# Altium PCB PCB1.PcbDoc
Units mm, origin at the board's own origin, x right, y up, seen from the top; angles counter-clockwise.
Board outline 33.5 x 35.78 mm, 2 copper layers (Top Layer, Bottom Layer); 48 components, 15 nets, 227 pads, 57 vias.
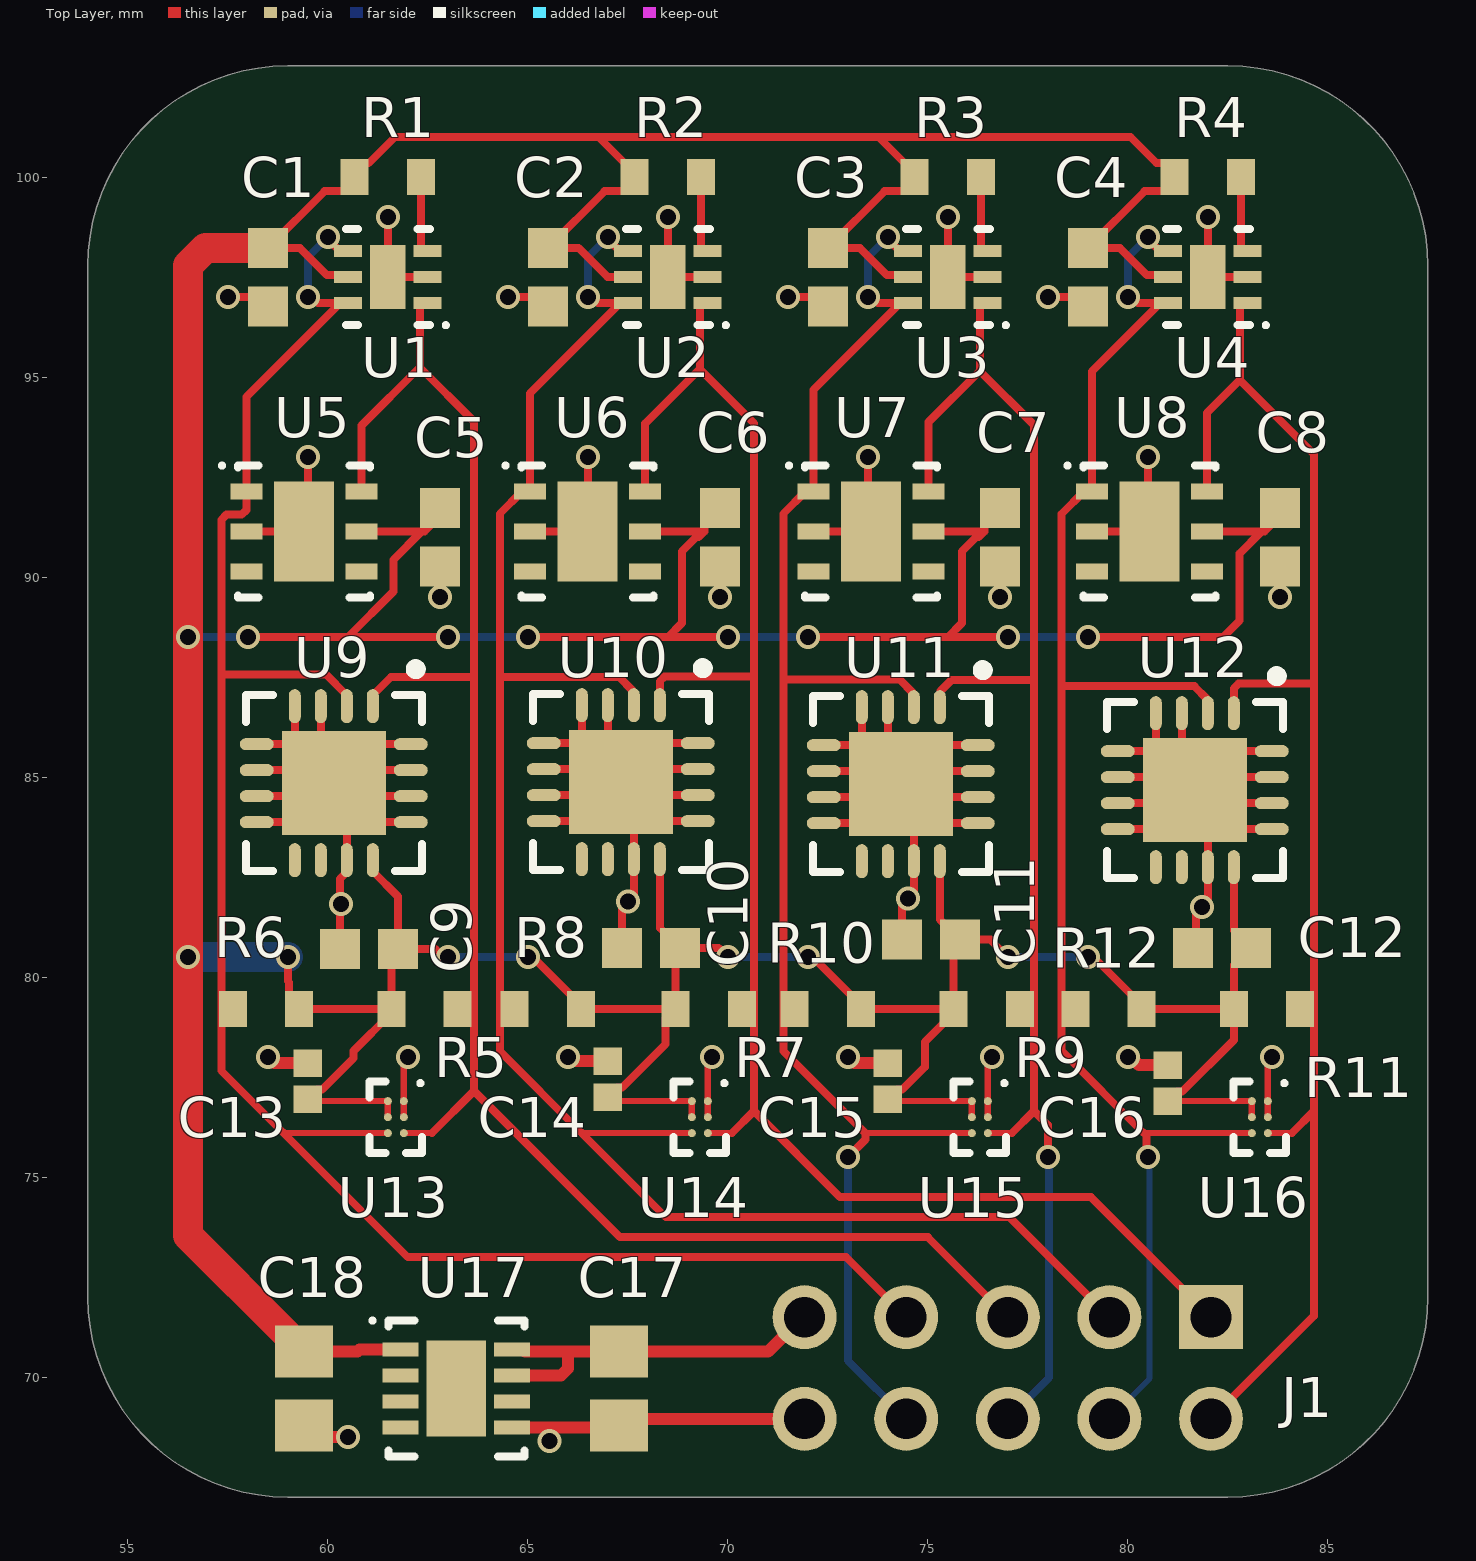
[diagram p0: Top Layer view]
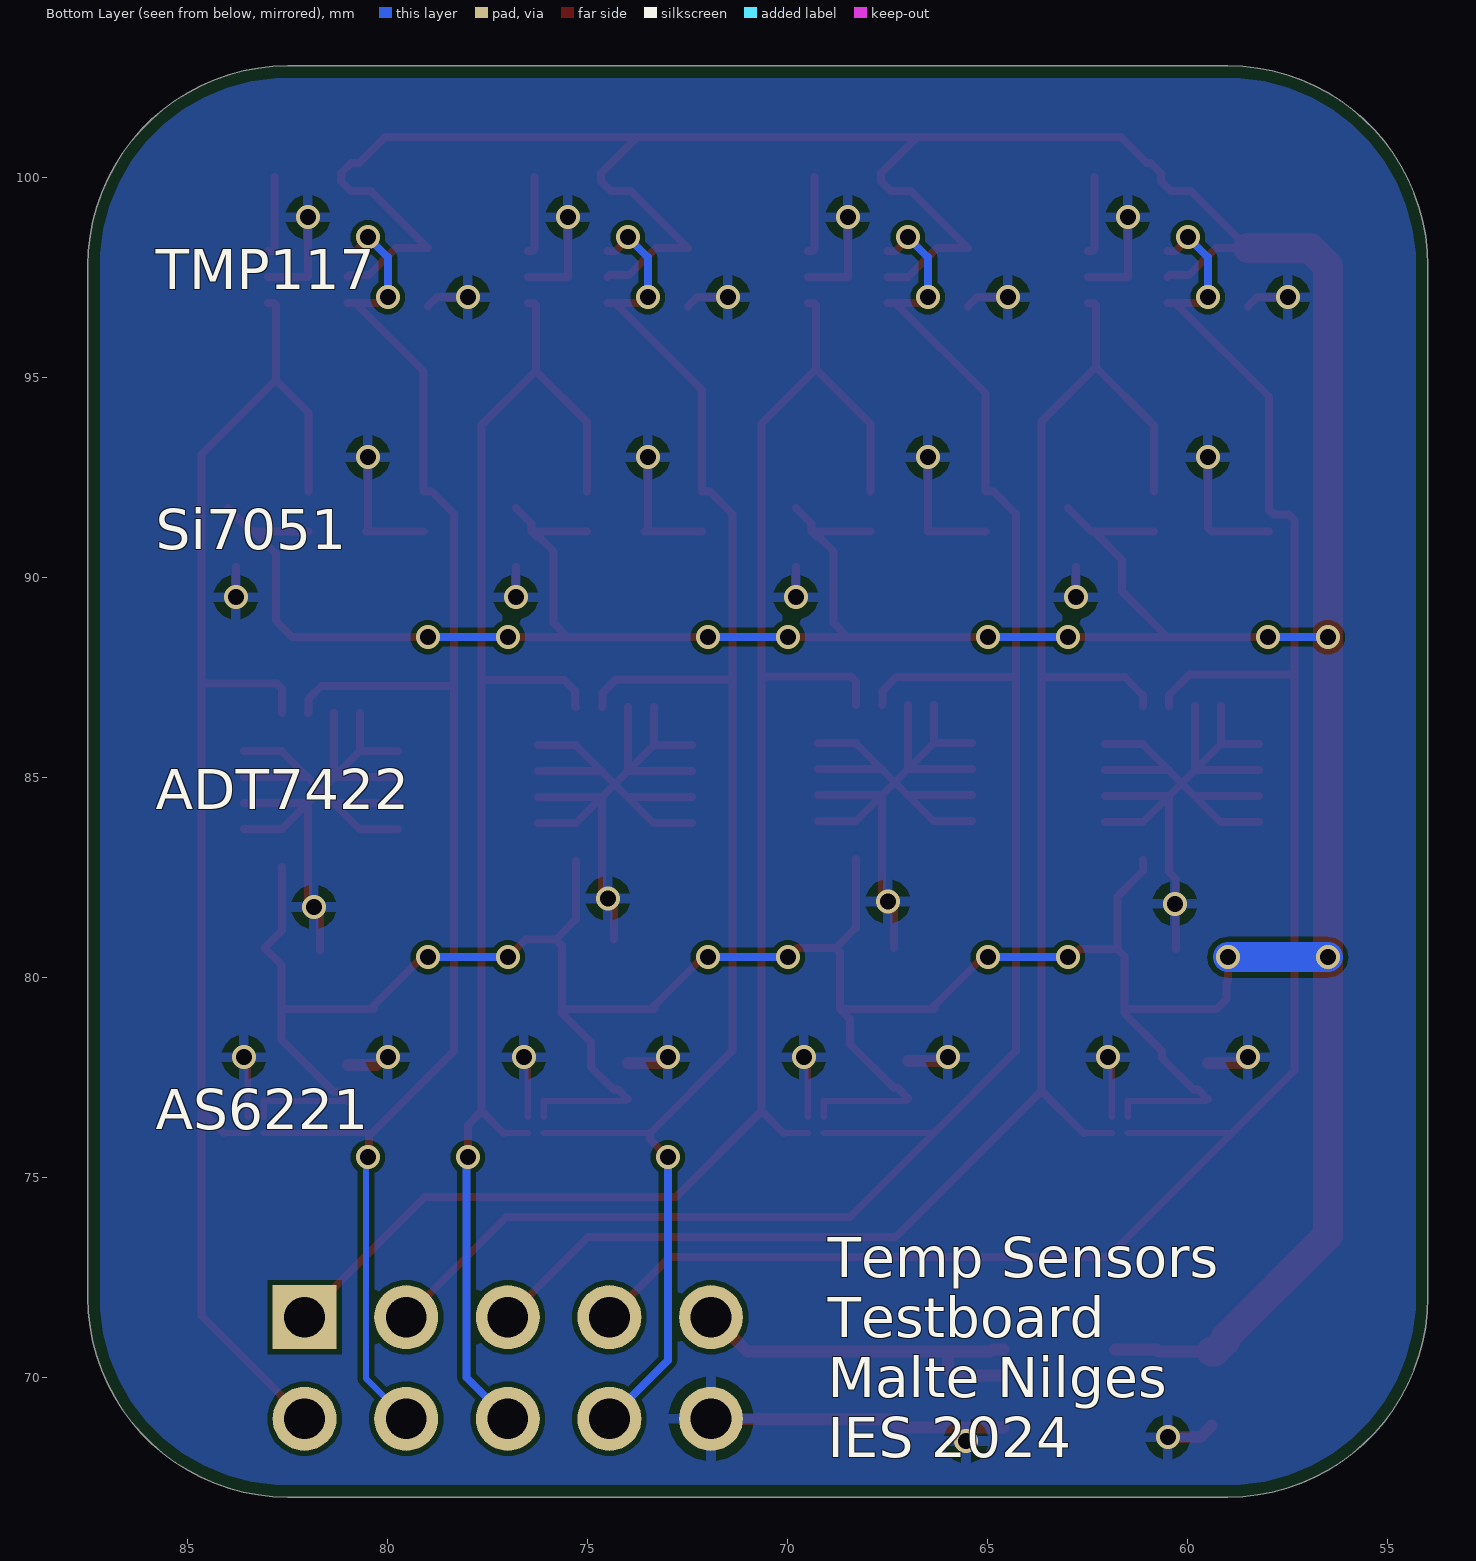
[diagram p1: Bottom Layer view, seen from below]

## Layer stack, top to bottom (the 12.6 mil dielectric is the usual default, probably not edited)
Top Solder: solder mask 0.0102, Solder Resist, Dk 3.5
Top Layer: signal copper 0.0356
Dielectric 1: dielectric 0.32, FR-4, Dk 4.8
Bottom Layer: signal copper 0.0356
Bottom Solder: solder mask 0.0102, Solder Resist, Dk 3.5

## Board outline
54,72 54,97.785 cw(c59,97.785) 59,102.785 82.5,102.785 cw(c82.5,97.785) 87.5,97.785 87.5,72 cw(c82.5,72) 82.5,67 59,67 cw(c59,72)

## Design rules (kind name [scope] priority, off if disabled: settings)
BoardOutlineClearance [All] p1: gap=0.3 ignorepadtopadclearanceinfootprint=FALSE
Clearance [All] p1: gap=0.127 ignorepadtopadclearanceinfootprint=FALSE
HoleToHoleClearance [All] p1: gap=0.5 allowstackedmicrovias=TRUE
MinimumSolderMaskSliver [All] p1: minsoldermaskwidth=0.1
PolygonConnect [All] p1: connectstyle=Relief reliefconductorwidth=0.254 reliefentries=4 polygonreliefangle="90 Angle" airgapwidth=0.254
RoutingVias [All] p1: holewidth=0.4 width=0.6 viastyle="Through Hole" minholewidth=0.3 minwidth=0.5 maxholewidth=1 maxwidth=2
SolderMaskExpansion [All] p1: expansion=0.05 istentingtop=FALSE
SupplyNets "Schematic Supply Nets_2" [InNet('GND')] p1: voltage=0.000
SupplyNets "Schematic Supply Nets_1" [InNet('3V3')] p2: voltage=0.000
SupplyNets "Schematic Supply Nets" [InNet('5V')] p3: voltage=0.000
Width [All] p1: maxlimit=2.54 minlimit=0.127 preferedwidth=0.254
28 further rules are at their usual default settings.

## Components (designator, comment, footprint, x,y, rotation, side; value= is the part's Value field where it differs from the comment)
C1 "100nF" CAP_SM0603_YAGEOCC2_N 58.5,97.5 r90 top
C2 "100nF" CAP_SM0603_YAGEOCC2_N 65.5,97.5 r90 top
C3 "100nF" CAP_SM0603_YAGEOCC2_N 72.5,97.5 r90 top
C4 "100nF" CAP_SM0603_YAGEOCC2_N 79,97.5 r90 top
C5 "100nF" CAP_SM0603_YAGEOCC2_N 62.8,91 r90 top
C6 "100nF" CAP_SM0603_YAGEOCC2_N 69.8,91 r90 top
C7 "100nF" CAP_SM0603_YAGEOCC2_N 76.8,91 r90 top
C8 "100nF" CAP_SM0603_YAGEOCC2_N 83.8,91 r90 top
C9 "100nF" CAP_SM0603_YAGEOCC2_N 61.028,80.699 r0 top
C10 "100nF" CAP_SM0603_YAGEOCC2_N 68.076,80.733 r0 top
C11 "100nF" CAP_SM0603_YAGEOCC2_N 75.076,80.938 r0 top
C12 "100nF" CAP_SM0603_YAGEOCC2_N 82.353,80.733 r0 top
C13 "10nF" CAP_SM0402_YAGEOCC2_N 59.5,77.4 r90 top
C14 "10nF" CAP_SM0402_YAGEOCC2_N 67,77.45 r90 top
C15 "10nF" CAP_SM0402_YAGEOCC2_N 74,77.4 r90 top
C16 "10nF" CAP_SM0402_YAGEOCC2_N 81,77.35 r90 top
C17 "1uF" CAP_SM0805_YAGEOCC2_N 67.28,69.714 r90 top
C18 "1uF" CAP_SM0805_YAGEOCC2_N 59.406,69.714 r90 top
J1 "PinHeader_2x5" PinHeader_2x5_2.54mm 82.08,71.5 r270 top
R1 "10K" RES_SM0603_YAGEORC_N 61.5,100 r0 top
R2 "10K" RES_SM0603_YAGEORC_N 68.5,100 r0 top
R3 "10K" RES_SM0603_YAGEORC_N 75.5,100 r0 top
R4 "10K" RES_SM0603_YAGEORC_N 82,100 r0 top
R5 "3K3" RES_SM0603_YAGEORC_N 62.415,79.199 r180 top
R6 "3K3" RES_SM0603_YAGEORC_N 58.454,79.199 r0 top
R7 "3K3" RES_SM0603_YAGEORC_N 69.523,79.199 r180 top
R8 "3K3" RES_SM0603_YAGEORC_N 65.5,79.199 r0 top
R9 "3K3" RES_SM0603_YAGEORC_N 76.472,79.199 r180 top
R10 "3K3" RES_SM0603_YAGEORC_N 72.5,79.199 r0 top
R11 "3K3" RES_SM0603_YAGEORC_N 83.479,79.199 r180 top
R12 "3K3" RES_SM0603_YAGEORC_N 79.521,79.199 r0 top
U1 "TMP117" TMP117(N/M)AIDRV_WSON 61.5,97.5 r180 top
U2 "TMP117" TMP117(N/M)AIDRV_WSON 68.5,97.5 r180 top
U3 "TMP117" TMP117(N/M)AIDRV_WSON 75.5,97.5 r180 top
U4 "TMP117" TMP117(N/M)AIDRV_WSON 82,97.5 r180 top
U5 "SI7051-A20-IMR" SI7050/1/2/3/4/5 59.405,91.139 r0 top
U6 "SI7051-A20-IMR" SI7050/1/2/3/4/5 66.493,91.139 r0 top
U7 "SI7051-A20-IMR" SI7050/1/2/3/4/5 73.581,91.139 r0 top
U8 "SI7051-A20-IMR" SI7050/1/2/3/4/5 80.542,91.139 r0 top
U9 "ADT7422CCPZ-RL7" ADT7422_QFN 60.15,84.85 r270 top
U10 "ADT7422CCPZ-RL7" ADT7422_QFN 67.325,84.875 r270 top
U11 "ADT7422CCPZ-RL7" ADT7422_QFN 74.325,84.825 r270 top
U12 "ADT7422CCPZ-RL7" ADT7422_QFN 81.675,84.675 r270 top
U13 "AS6221" AS6221_BGA 61.7,76.5 r270 top
U14 "AS6221" AS6221_BGA 69.3,76.5 r270 top
U15 "AS6221" AS6221_BGA 76.3,76.5 r270 top
U16 "AS6221" AS6221_BGA 83.3,76.5 r270 top
U17 "TPS78433" TPS784xxxQDRBRQ1_SON 63.216,69.714 r0 top

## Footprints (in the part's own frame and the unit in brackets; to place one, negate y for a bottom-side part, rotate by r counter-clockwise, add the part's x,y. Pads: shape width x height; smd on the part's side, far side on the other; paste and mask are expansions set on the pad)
ADT7422_QFN [mm] "QFN, 16-Leads, Body 4,00x4,00mm, Pitch 0,65mm, Thermal Pad 2,60x2,60mm, IPC Medium Density"
  oval 0.85x0.3 smd: 1(-1.925,0.975) 2(-1.925,0.325) 3(-1.925,-0.325) 4(-1.925,-0.975) 9(1.925,-0.975) 10(1.925,-0.325) 11(1.925,0.325) 12(1.925,0.975)
  oval 0.3x0.85 smd: 5(-0.975,-1.925) 6(-0.325,-1.925) 7(0.325,-1.925) 8(0.975,-1.925) 13(0.975,1.925) 14(0.325,1.925) 15(-0.325,1.925) 16(-0.975,1.925)
  rect 2.6x2.6 smd: 17(0,0)
  silkscreen extent -2.97,-2.2 2.2,2.2, body extent -2.05,-2.05 2.05,2.05, height 0.8
AS6221_BGA [mm] "BGA, 6-Leads, Body 1,02x1,50mmx0,53mm, Pitch 0,40mm"
  round 0.2 smd: A1(-0.4,0.2) A2(0,0.2) A3(0.4,0.2) B1(-0.4,-0.2) B2(0,-0.2) B3(0.4,-0.2)
  silkscreen extent -0.9,-0.66 0.89,0.66, body extent -0.74,-0.51 0.74,0.51, height 0.55
CAP_SM0402_YAGEOCC2_N [mm] "Capacitor, Yageo CC Class2, SM0402, IPC Medium Density"
  rect 0.68x0.72 smd: 1(-0.45,0) 2(0.45,0)
  body extent -0.55,-0.35 0.55,0.35, height 0.6
CAP_SM0603_YAGEOCC2_N [mm] "Capacitor, Yageo CC Class2, SM0603, IPC Medium Density"
  rect 1x1 smd: 1(-0.727,0) 2(0.727,0)
  body extent -0.9,-0.5 0.9,0.5, height 0.9
CAP_SM0805_YAGEOCC2_N [mm] "Capacitor, Yageo CC Class2, SM0805, IPC Medium Density"
  rect 1.3x1.45 smd: 1(-0.927,0) 2(0.927,0)
  body extent -1.1,-0.72 1.1,0.72, height 1.45
PinHeader_2x5_2.54mm [mm]
  rect 1.6x1.6 hole 1.02: 1(0,0)
  round 1.6 hole 1.02: 2(2.54,0) 3(0,-2.54) 4(2.54,-2.54) 5(0,-5.08) 6(2.54,-5.08) 7(0,-7.62) 8(2.54,-7.62) 9(0,-10.16) 10(2.54,-10.16)
RES_SM0603_YAGEORC_N [mm] "Resistor, Yageo RC_L, SM0603, IPC Medium Density"
  rect 0.7x0.9 smd: 1(-0.827,0) 2(0.827,0)
  body extent -0.85,-0.45 0.85,0.45, height 0.55
SI7050/1/2/3/4/5 [mm] "SON, 6-Leads, Body 3,00x3,00mm, Pitch 1,00mm, Thermal Pad 2,50x1,50mm, IPC Medium Density"
  rect 0.8x0.4 smd: 1(-1.44,1) 2(-1.44,0) 3(-1.44,-1) 4(1.44,-1) 5(1.44,0) 6(1.44,1)
  rect 1.5x2.5 smd: 7(0,0)
  silkscreen extent -2.1,-1.65 1.65,1.7, body extent -1.5,-1.5 1.5,1.5, height 0.8
TMP117(N/M)AIDRV_WSON [mm] "SON127P600-8N"
  rect 0.7x0.3 smd: 1(-0.995,0.65) 2(-0.995,0) 3(-0.995,-0.65) 4(0.995,-0.65) 5(0.995,0) 6(0.995,0.65)
  rect 0.89x1.6 smd: 7(0,0)
  silkscreen extent -1.5,-1.2 1.05,1.25, body extent -1.05,-1.05 1.05,1.05, height 0.8
TPS784xxxQDRBRQ1_SON [mm] "SON127P600-8N"
  rect 0.9x0.35 smd: 1(-1.395,0.975) 2(-1.395,0.325) 3(-1.395,-0.325) 4(-1.395,-0.975) 5(1.395,-0.975) 6(1.395,-0.325) 7(1.395,0.325) 8(1.395,0.975)
  rect 1.49x2.4 smd: 9(0,0)
  silkscreen extent -2.15,-1.7 1.7,1.75, body extent -1.55,-1.55 1.55,1.55, height 1

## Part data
C1 C2 C3 C4 C5 C6 C7 C8 C9 C10 C11 C12: library part CC0603KRX7R9BB104, "CAP 100nF SM0603 X7R 50V YAGEO CC2", Manufacturer=Yageo, Package=0603, Supplier Part Number 1=1362556, Tolerance (%)=10, Voltage Rating (Volts)=50
C13 C14 C15 C16: library part CC0402KRX7R9BB103, "CAP 10nF SM0402 X7R 50V YAGEO CC2", Manufacturer=Yageo, Manufacturer Part Number=CC0603KRX7R9BB103, Package=0603, Supplier Part Number 1=3369167, Tolerance (%)=10, Voltage Rating (Volts)=50
C17 C18: library part CC0805KKX7R8BB105, "CAP 1uF SM0805 X7R 25V YAGEO CC2", Manufacturer=Yageo, Package=0805, Supplier Part Number 1=1458903, Tolerance (%)=10, Voltage Rating (Volts)=25
J1: library part PinHeader_2x5_2.54mm, "PinHeader_2x5 2.54mm Pitch"
R1 R2 R3 R4: library part RC0603FR-0710KL, "RES 10K SM0603 YAGEO RC_L", Manufacturer=Yageo, Package=0603, Power (Watts)=0.1, Resistance (Ohms)=10000, Supplier Part Number 1=9238603, Tolerance (%)=1
R5 R6 R7 R8 R9 R10 R11 R12: library part RC0603FR-073K3L, "RES 3.3K SM0603 YAGEO RC_L", Manufacturer=Yageo, Manufacturer Part Number=RC0603FR-0710KL, Package=0603, Power (Watts)=0.1, Resistance (Ohms)=10000, Supplier Part Number 1=6497630, Supplier Part Number 10=311-3.30KHRCT-ND, Supplier Part Number 11=311-3.30KHRDKR-ND, Supplier Part Number 12=311-3.30KHRTR-ND, Tolerance (%)=1
U1 U2 U3 U4: library part TMP117NAIDRVR, "TMP117 High-Accuracy, Low-Power, Digital Temperature Sensor, -55°C bis 150°C, 16b 6-WSON (2x2)", Supplier Part Number 1=595-TMP117NAIDRVR
U5 U6 U7 U8: "Si7051-A20 Temperature Sensor ±0.1°C maximum accuracy, Digital I2C, -40°C ~ 125°C 14b 6-DFN (3x3)", Supplier Part Number 1=3265013RL
U9 U10 U11 U12: "ADT7422 Temperature Sensor, ±0.1°C Accuracy, 16b, Digital I2C /  -40°C bis 125°C 16-LFCSP-WQ (4x4)", Supplier Part Number 1=584-ADT7422CCPZ-RL7
U13 U14 U15 U16: library part AS6221-AWLT-S, "AS6221 Temperature Sensor Digital -40°C ~ 125°C 16b 6-WLCSP (1.5x1.03)", Supplier Part Number 1=985-AS6221-AWLT-S
U17: library part TPS78433QWDRBRQ1, "TPS78433-Q1 3.3V, 300-mA, High-PSRR Low-Dropout Voltage Regulator With High Accuracy and Enable,  8-SON (3x3)", Supplier Part Number 1=595-TPS78433QWDRBRQ1

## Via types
v1: diameter 0.6, hole 0.4, Top Layer to Bottom Layer, 57 vias

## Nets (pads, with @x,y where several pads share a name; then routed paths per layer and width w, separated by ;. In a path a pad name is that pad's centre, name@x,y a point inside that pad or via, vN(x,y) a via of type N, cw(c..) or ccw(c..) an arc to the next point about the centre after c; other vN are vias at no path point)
3V3: C1.2 C2.2 C3.2 C4.2 C5.2 C6.2 C7.2 C8.2 C9.2 C10.2 C11.2 C12.2 C13.1 C14.1 C15.1 C16.1 C18.2 R1.1 R2.1 R3.1 R4.1 R5.2 R6.2 R7.2 R8.2 R9.2 R10.2 R11.2 R12.2 U1.5 U2.5 U3.5 U4.5 U5.5 U6.5 U7.5 U8.5 U9.12 U10.12 U11.12 U12.12 U13.B1 U13.B2 U14.B1 U14.B2 U15.B1 U15.B2 U16.B1 U16.B2 U17.1 | length 192.9
  Top Layer w0.152: C13.1 59.55,76.9 U13.B1 U13.B2 ; C14.1@67,76.95 67.05,76.9 U14.B1 U14.B2 ; C15.1 74.05,76.9 U15.B1 U15.B2 ; C16.1 U16.B1 U16.B2
  Top Layer w0.2: v1(58,88.5) 60.5,88.5 ; v1(59,80.5) 59,79.9 59.031,79.869 59.031,79.449 R6.2 R5.2 ; C13.1 59.74,77.19 59.861,77.19 60.646,77.975 60.646,78.157 61.588,79.099 R5.2 ; U1.5 60.455,97.55 59.977,97.55 59.3,98.227 C1.2 59.923,99.65 60.423,99.65 60.673,99.9 R1.1 60.673,100.1 60.923,100.35 61.023,100.35 61.673,101 66.773,101 ; U5.5 62.345,91.139 ; U9.12 61.125,82.65 61.755,82.02 C9.2 ; v1(63,80.5) 62.892,80.5 62.693,80.699 C9.2 ; v1(63,88.5) 60.5,88.5 ; C5.2@63,91.727 62.412,91.139 62.345,91.139 ; v1(65,80.5) 65.077,80.423 65.203,80.423 66.327,79.299 R8.2 R7.2 ; v1(65,88.5) 68.5,88.5 ; C14.1@67,76.95 67,76.98 67.26,77.24 67.361,77.24 68.446,78.325 68.446,78.949 R7.2 ; U2.5 67.495,97.51 66.99,97.51 66.273,98.227 C2.2 66.923,99.65 67.423,99.65 67.673,99.9 R2.1 67.673,100.1 66.773,101 ; U6.5 69.412,91.139 ; U10.12 68.3,81.236 C10.2 ; C6.2 69.412,91.339 69.412,91.139 ; v1(70,80.5) 69.767,80.733 C10.2 ; v1(70,88.5) 68.5,88.5 ; v1(72,80.5) 72.077,80.423 72.203,80.423 73.327,79.299 R10.2 R9.2 ; v1(72,88.5) 75.5,88.5 ; C15.1 74.24,77.19 74.361,77.19 74.925,77.754 74.925,78.379 75.645,79.099 R9.2 ; U3.5 74.455,97.55 73.977,97.55 73.3,98.227 C3.2 73.923,99.65 74.423,99.65 74.673,99.9 R3.1 74.673,100.1 73.773,101 ; U7.5 76.412,91.139 ; U11.12 75.3,81.441 C11.2 ; C7.2 76.412,91.339 76.412,91.139 ; v1(77,80.5) 76.562,80.938 C11.2 ; v1(77,88.5) 75.5,88.5 ; v1(79,80.5) 79.077,80.423 79.224,80.423 80.348,79.299 R12.2 R11.2 ; v1(79,88.5) 82.383,88.5 82.794,88.912 82.794,90.588 83.345,91.139 ; C16.1 81.24,77.14 81.361,77.14 82.652,78.431 R11.2 ; U4.5 80.955,97.55 80.477,97.55 79.8,98.227 C4.2 80.423,99.65 80.923,99.65 81.173,99.9 R4.1 81.173,100.1 80.923,100.35 80.723,100.35 80.073,101 73.773,101 ; U8.5 83.345,91.139 ; U12.12 82.65,81.165 C12.2 ; C12.2 82.652,80.305 R11.2 ; C8.2@84,91.727 83.412,91.139 83.345,91.139 ; 60.5,88.5 61.641,89.641 61.641,90.435 62.345,91.139 ; R5.2 61.588,80.532 C9.2 ; 66.773,101 73.773,101 ; 68.5,88.5 68.853,88.853 68.853,90.647 69.206,91 69.273,91 69.412,91.139 ; R7.2 68.696,80.626 C10.2 ; 75.5,88.5 75.853,88.853 75.853,90.647 76.206,91 76.273,91 76.412,91.139 ; R9.2 75.645,80.78 C11.2
  Top Layer w0.3: C18.2 60.74,70.641 60.788,70.689 U17.1
  Top Layer w0.75: C1.2 56.939,98.227 56.5,97.788 v1(56.5,88.5) v1(56.5,80.5) 56.5,73.547 59.056,70.991 59.056,70.916 59.331,70.641 C18.2
  Bottom Layer w0.2: v1(56.5,88.5) v1(58,88.5) ; v1(63,80.5) v1(65,80.5) ; v1(63,88.5) v1(65,88.5) ; v1(70,80.5) v1(72,80.5) ; v1(70,88.5) v1(72,88.5) ; v1(77,80.5) v1(79,80.5) ; v1(77,88.5) v1(79,88.5)
  Bottom Layer w0.75: v1(56.5,80.5) v1(59,80.5)
5V: C17.2 J1.9 U17.7 U17.8 | length 9.6
  Top Layer w0.3: U17.7 65.824,70.039 66,70.215 66,70.534 66.107,70.641 ; U17.8 64.886,70.689 64.934,70.641 66.107,70.641 ; J1.9 71.87,71.5 71.011,70.641 C17.2 66.107,70.641
GND: C1.1 C2.1 C3.1 C4.1 C5.1 C6.1 C7.1 C8.1 C9.1 C10.1 C11.1 C12.1 C13.2 C14.2 C15.2 C16.2 C17.1 C18.1 J1.10 U1.2 U1.7 U2.2 U2.7 U3.2 U3.7 U4.2 U4.7 U5.2 U5.7 U6.2 U6.7 U7.2 U7.7 U8.2 U8.7 U9.3 U9.4 U9.5 U9.6 U9.7 U9.8 U9.11 U9.13 U9.14 U9.15 U9.16 U9.17 U10.3 U10.4 U10.5 U10.6 U10.7 U10.8 U10.11 U10.13 U10.14 U10.15 U10.16 U10.17 U11.3 U11.4 U11.5 U11.6 U11.7 U11.8 U11.11 U11.13 U11.14 U11.15 U11.16 U11.17 U12.3 U12.4 U12.5 U12.6 U12.7 U12.8 U12.11 U12.13 U12.14 U12.15 U12.16 U12.17 U13.A1 U13.A2 U14.A1 U14.A2 U15.A1 U15.A2 U16.A1 U16.A2 U17.5 | length 137.8
  Top Layer w0.152: U13.A2 U13.A1 61.9,77.779 62,77.879 v1(62,78) ; U14.A2 U14.A1 69.5,77.779 69.6,77.879 v1(69.6,78) ; U15.A2 U15.A1 76.5,77.779 76.6,77.879 v1(76.6,78) ; U16.A2 U16.A1 83.5,77.779 83.6,77.879 v1(83.6,78)
  Top Layer w0.2: v1(57.5,97) 58.273,97 C1.1 ; U5.2 U5.7 59.5,91.234 v1(59.5,93) ; U9.8 59.175,83.875 U9.17@59.825,84.525 ; U9.7 U9.17@59.825,84.525 ; U9.6 U9.17@59.825,85.175 ; U9.5 U9.17@59.175,85.825 ; U9.4 U9.17@59.175,85.825 ; U9.3 U9.17@59.825,85.175 ; C9.1 60.301,82.455 60.475,82.629 U9.11 U9.17@60.475,84.525 ; v1(61.5,99) U1.7 U1.2 ; U9.13 61.125,83.875 U9.17@60.475,84.525 ; U9.14 U9.17@60.475,84.525 ; U9.15 U9.17@60.475,85.175 ; U9.16 61.125,85.825 U9.17@60.475,85.175 ; v1(62.8,89.5) C5.1 ; v1(64.5,97) 65.273,97 C2.1 ; U6.2 U6.7 ; U10.8 66.35,83.9 U10.17@67,84.55 ; U10.7 U10.17@67,84.55 ; U10.6 U10.17@67,85.2 ; U10.5 U10.17@66.35,85.85 ; U10.4 U10.17@66.35,85.85 ; U6.7@66.5,91.234 v1(66.5,93) ; U10.3 U10.17@67,85.2 ; C10.1 67.349,81.74 67.65,82.041 U10.11 U10.17@67.65,84.55 ; v1(68.5,99) U2.7 U2.2 ; U10.13 68.3,83.9 U10.17@67.65,84.55 ; U10.14 U10.17@67.65,84.55 ; U10.15 U10.17@67.65,85.2 ; U10.16 68.3,85.85 U10.17@67.65,85.2 ; v1(69.8,89.5) C6.1 ; v1(71.5,97) 72.273,97 C3.1 ; U7.2 U7.7 ; U11.8 73.35,83.85 U11.17@74,84.5 ; U11.7 U11.17@74,84.5 ; U11.6 U11.17@74,85.15 ; U11.5 U11.17@73.35,85.8 ; U11.4 U11.17@73.35,85.8 ; U7.7@73.5,91.234 v1(73.5,93) ; U11.3 U11.17@74,85.15 ; C11.1 74.349,81.817 74.65,82.118 U11.11 U11.17@74.65,84.5 ; v1(75.5,99) U3.7 U3.2 ; U11.13 75.3,83.85 U11.17@74.65,84.5 ; U11.14 U11.17@74.65,84.5 ; U11.15 U11.17@74.65,85.15 ; U11.16 75.3,85.8 U11.17@74.65,85.15 ; v1(76.8,89.5) C7.1 ; v1(78,97) 78.773,97 C4.1 ; U8.2 U8.7 ; U12.8 80.7,83.7 U12.17@81.35,84.35 ; U12.7 U12.17@81.35,84.35 ; U12.6 U12.17@81.35,85 ; U12.5 U12.17@80.7,85.65 ; U8.7@80.5,91.234 v1(80.5,93) ; U12.4 U12.17@80.7,85.65 ; U12.3 U12.17@81.35,85 ; C12.1@81.699,80.662 81.699,81.604 82,81.905 U12.11 U12.17@82,84.35 ; v1(82,99) U4.7 U4.2 ; U12.13 82.65,83.7 U12.17@82,84.35 ; U12.14 U12.17@82,84.35 ; U12.15 U12.17@82,85 ; U12.16 82.65,85.65 U12.17@82,85 ; v1(83.8,89.5) C8.1 ; U9.17@59.175,85.825 U9.17@59.825,85.175 ; U9.17@59.825,84.525 U9.17 ; U9.17@59.825,85.175 U9.17 ; U9.17 U9.17@60.475,84.525 ; U9.17 U9.17@60.475,85.175 ; U10.17@66.35,85.85 U10.17@67,85.2 ; U10.17@67,84.55 U10.17 ; U10.17@67,85.2 U10.17 ; U10.17 U10.17@67.65,85.2 ; U10.17 U10.17@67.65,84.55 ; U11.17@73.35,85.8 U11.17@74,85.15 ; U11.17@74,84.5 U11.17 ; U11.17@74,85.15 U11.17 ; U11.17 U11.17@74.65,85.15 ; U11.17 U11.17@74.65,84.5 ; U12.17@80.7,85.65 U12.17@81.35,85 ; U12.17@81.35,84.35 U12.17 ; U12.17@81.35,85 U12.17 ; U12.17 U12.17@82,85 ; U12.17 U12.17@82,84.35
  Top Layer w0.3: v1(58.5,78) 58.65,77.85 C13.2 ; C18.1 59.693,68.5 v1(60.5,68.5) ; U17.5 67.232,68.739 C17.1 67.453,68.96 J1.10 ; v1(66,78) 66.081,78 66.181,77.9 C14.2 ; v1(73,78) 73.15,77.85 C15.2 ; v1(80,78) 80.081,78 80.281,77.8 C16.2
  other v1: 65.544,68.406 81.85,81.755 60.324,81.836 67.5,81.89 74.5,81.968
NetR1_2: R1.2 U1.3 | length 2
  Top Layer w0.2: R1.2 62.327,98.2 62.377,98.15 U1.3
NetR2_2: R2.2 U2.3 | length 2
  Top Layer w0.2: R2.2 69.327,98.2 69.377,98.15 U2.3
NetR3_2: R3.2 U3.3 | length 2
  Top Layer w0.2: R3.2 76.327,98.2 76.377,98.15 U3.3
NetR4_2: R4.2 U4.3 | length 2
  Top Layer w0.2: R4.2 82.827,98.2 82.877,98.15 U4.3
SCL1: J1.5 R5.1 U1.1 U5.6 U9.1 U13.A3 | length 45
  Top Layer w0.152: U13.A3 62.6,76.1
  Top Layer w0.2: U5.6 60.845,93.793 62.299,95.246 ; U9.1 61.125,87.05 61.575,87.5 63.654,87.5 ; U1.1 62.349,96.85 62.299,96.8 62.299,95.246 ; 62.6,76.1 63.654,77.154 ; J1.5 75,73.5 67.308,73.5 63.654,77.154 ; 62.299,95.246 63.654,93.891 63.654,87.5 ; 63.654,77.154 63.654,87.5
SCL2: J1.1 R7.1 U2.1 U6.6 U10.1 U14.A3 | length 42.5
  Top Layer w0.152: U14.A3 70.1,76.1
  Top Layer w0.2: U6.6 67.933,93.837 69.299,95.202 ; U10.1 68.3,87.397 68.417,87.514 70.654,87.514 ; U2.1 69.349,96.85 69.299,96.8 69.299,95.202 ; 70.1,76.1 70.654,76.654 ; J1.1 79.08,74.5 72.808,74.5 70.654,76.654 ; 69.299,95.202 70.654,93.847 70.654,87.514 ; 70.654,76.654 70.654,87.514
SCL3: J1.6 R9.1 U3.1 U7.6 U11.1 U15.A3 | length 37
  Top Layer w0.152: U15.A3 77.1,76.1
  Top Layer w0.2: U7.6 75.021,93.881 76.299,95.158 ; U11.1 75.319,86.769 75.319,87.152 75.596,87.429 77.654,87.429 ; U3.1 76.349,96.85 76.299,96.8 76.299,95.158 ; 77.1,76.1 77.654,76.654 ; v1(78,75.5) 78,76.308 77.654,76.654 ; 76.299,95.158 77.654,93.803 77.654,89.379 77.654,87.429 ; 77.654,76.654 77.654,87.429
  Bottom Layer w0.2: J1.6 78.027,69.987 78.027,75.473 v1(78,75.5)
SCL4: J1.2 R11.1 U4.1 U8.6 U12.1 U16.A3 | length 37.1
  Top Layer w0.152: U16.A3 84.1,76.1
  Top Layer w0.2: U8.6 81.982,94.111 82.799,94.928 ; J1.2 84.654,71.534 84.654,76.654 ; U12.1 82.65,87.219 82.767,87.336 84.654,87.336 ; U4.1 82.849,96.85 82.799,96.8 82.799,94.928 ; 84.1,76.1 84.654,76.654 ; 82.799,94.928 84.654,93.073 84.654,89.429 84.654,88.879 84.654,87.336 ; 84.654,76.654 84.654,87.336
SDA1: J1.7 R6.1 U1.4 U1.6 U5.1 U9.2 U13.B3 | length 50
  Top Layer w0.152: 58.9,76.1 U13.B3
  Top Layer w0.2: v1(59.5,97) 59.608,97 59.758,96.85 U1.6@60.305,96.85 ; v1(60,98.5) 60,98.455 60.305,98.15 U1.4 ; U9.2 60.475,87.05 59.959,87.566 57.338,87.566 ; U1.6 U1.6@60.305,96.85 ; J1.7 72.96,73 62,73 58.9,76.1 57.338,77.662 57.338,79.199 57.338,87.566 ; 57.338,87.566 57.338,91.433 57.471,91.566 57.848,91.566 57.965,91.683 U5.1 57.965,94.51 U1.6@60.305,96.85
  Bottom Layer w0.2: v1(59.5,97) 59.5,98 v1(60,98.5)
SDA2: J1.3 R8.1 U2.4 U2.6 U6.1 U10.2 U14.B3 | length 48.1
  Top Layer w0.152: 66.351,76.1 U14.B3
  Top Layer w0.2: v1(66.5,97) 66.608,97 66.758,96.85 U2.6@67.305,96.85 ; v1(67,98.5) 67,98.455 67.305,98.15 U2.4 ; U2.6 U2.6@67.305,96.85 ; U10.2 67.631,86.819 67.631,87.157 67.279,87.509 64.299,87.509 ; J1.3 77.04,74 68.451,74 66.351,76.1 64.299,78.152 64.299,87.509 ; 64.299,87.509 64.299,91.585 64.853,92.139 U6.1 65.053,94.598 U2.6@67.305,96.85
  Bottom Layer w0.2: v1(66.5,97) 66.5,98 v1(67,98.5)
SDA3: J1.8 R10.1 U3.4 U3.6 U7.1 U11.2 U15.B3 | length 40.7
  Top Layer w0.152: 73.439,76.1 U15.B3
  Top Layer w0.2: v1(73,75.5) 73.439,75.939 73.439,76.1 71.387,78.152 71.387,79.199 71.387,87.441 ; v1(73.5,97) 73.608,97 73.758,96.85 U3.6@74.305,96.85 ; v1(74,98.5) 74,98.455 74.305,98.15 U3.4 ; U3.6 U3.6@74.305,96.85 ; U11.2 74.631,86.769 74.631,87.107 74.297,87.441 71.387,87.441 ; 71.387,87.441 71.387,91.585 71.941,92.139 U7.1 72.141,94.686 U3.6@74.305,96.85
  Bottom Layer w0.2: v1(73,75.5) 73,70.42 J1.8 ; v1(73.5,97) 73.5,98 v1(74,98.5)
SDA4: J1.4 R12.1 U4.4 U4.6 U8.1 U12.2 U16.B3 | length 40.6
  Top Layer w0.152: v1@80.471,75.529 v1(80.5,75.5) ; 80.471,76.029 80.4,76.1 U16.B3
  Top Layer w0.2: v1(80,97) 80.108,97 80.258,96.85 U4.6@80.805,96.85 ; 80.4,76.1 78.348,78.152 78.348,87.275 ; v1@80.471,75.529 80.471,76.029 ; v1(80.5,98.5) 80.5,98.455 80.805,98.15 U4.4 ; U4.6 U4.6@80.805,96.85 ; U12.2 81.981,86.619 81.981,86.957 81.663,87.275 78.348,87.275 ; 78.348,87.275 78.348,91.585 78.902,92.139 U8.1 79.102,95.147 U4.6@80.805,96.85
  Bottom Layer w0.152: J1.4 80.543,69.963 80.543,75.457 v1(80.5,75.5)
  Bottom Layer w0.2: v1(80,97) 80,98 v1(80.5,98.5)
pads on no net: U5.3 U5.4 U6.3 U6.4 U7.3 U7.4 U8.3 U8.4 U9.9 U9.10 U10.9 U10.10 U11.9 U11.10 U12.9 U12.10 U17.2 U17.3 U17.4 U17.6 U17.9

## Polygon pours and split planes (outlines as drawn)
GND on Bottom Layer "GND_L02_P000" (solid, pour order 0): 54,102.785 54,67 87.5,67 87.5,102.785

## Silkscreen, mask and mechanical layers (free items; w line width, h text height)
Bottom Overlay:
  text "TMP117" at 85.8,97.2 h1
  text "Si7051" at 85.8,90.7 h1
  text "ADT7422" at 85.8,84.2 h1
  text "AS6221" at 85.8,76.2 h1
  text "Temp Sensors / Testboard / Malte Nilges / IES 2024" at 69,68 h1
